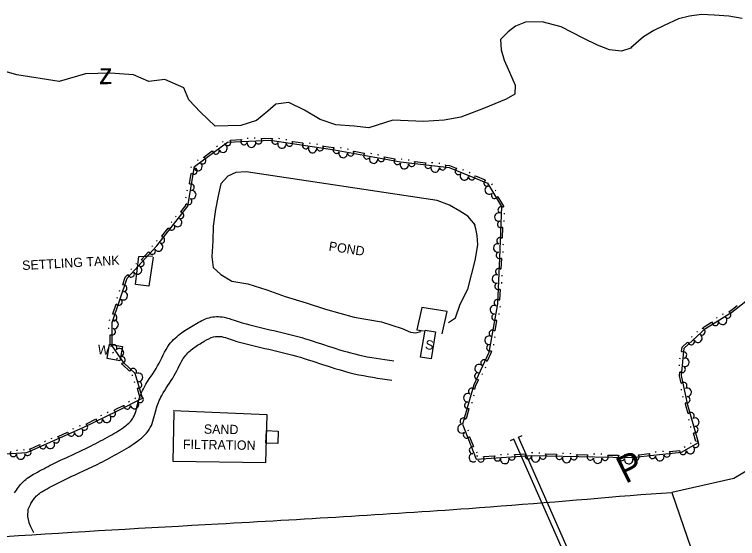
# Model space of a CAD drawing. Extents: x 2030130 to 2036320, y 723205 to 762423.
# Drawn here: x 2034679.9 to 2034966.6, y 761073.1 to 761281.1 of the extents above; entities that cross this region are included whole.
import ezdxf

# ---------------------------------------------------------------- set-up
doc = ezdxf.new("R2010")
doc.units = 0
for name, color, linetype in [('Draft_Station Labels Major', 7, 'Continuous'), ('Draft_Station Tics Major', 7, 'Continuous'), ('Draft_Station Tics Minor', 7, 'Continuous'), ('Exist Terrain Model Ground Surface', 7, 'Continuous'), ('Old_Level_28', 7, 'Continuous'), ('Prop Alignment Horizontal', 7, 'Continuous'), ('Prop Alignment Vertical', 7, 'Continuous'), ('Prop Horizontal Alignment Ramp', 7, 'Continuous')]:
    doc.layers.add(name, color=color, linetype=linetype)

msp = doc.modelspace()

# ---------------------------------------------------------------- linework, layer by layer
at = {"layer": 'Draft_Station Labels Major'}
for points in [[(2034992.98, 761113.37), (2034965.16, 761096.91), (2034940.63, 761091.38), (2034996.55, 760928.45)], [(2034928.25, 761090.56), (2034940.63, 761091.38)], [(2034686.36, 761087.04), (2034685.25, 761084.65), (2034685.11, 761081.9), (2034685.64, 761079.51), (2034686.26, 761077.85), (2034686.92, 761076.49), (2034687.39, 761075.48)]]:
    msp.add_lwpolyline(points, dxfattribs=at)
for points in [[(2034679.89, 761091.18), (2034683.28, 761095.59), (2034688.12, 761098.96), (2034694.94, 761102.58), (2034703.68, 761106.71), (2034710.37, 761109.9), (2034717.65, 761113.84), (2034723.88, 761117.76), (2034727.01, 761121.11), (2034728.85, 761126.85), (2034731.44, 761133.34), (2034736.68, 761141.63), (2034741.3, 761150.08), (2034746.26, 761154.8), (2034751.43, 761158.08), (2034757.08, 761160.74), (2034762.99, 761160.9), (2034767.05, 761159.7), (2034792.31, 761153.26), (2034816.36, 761145.98), (2034830.34, 761143.61)], [(2034686.36, 761087.04), (2034688.62, 761089.99), (2034692.11, 761092.42), (2034698.37, 761095.74), (2034706.95, 761099.8), (2034713.84, 761103.08), (2034721.52, 761107.24), (2034728.78, 761111.82), (2034733.77, 761117.13), (2034736.05, 761124.26), (2034738.28, 761129.85), (2034743.27, 761137.75), (2034747.44, 761145.36), (2034750.99, 761148.75), (2034755.12, 761151.37), (2034758.88, 761153.14), (2034761.99, 761153.22), (2034765.03, 761152.33), (2034790.26, 761145.89), (2034814.6, 761138.52), (2034829.55, 761135.98)], [(2034092.04, 760960.15), (2034128.02, 760985.27), (2034167.72, 761010.14), (2034207.02, 761028.78), (2034238.75, 761041.08), (2034290.36, 761053.26), (2034339.84, 761057.27), (2034410.92, 761061), (2034496.35, 761063.49), (2034597.04, 761068.5), (2034676.22, 761073.92), (2034760.74, 761078.95), (2034860.07, 761085.08), (2034928.36, 761090.57)]]:
    msp.add_spline(points, degree=3, dxfattribs=at)
at = {"layer": 'Draft_Station Tics Major'}
for points in [[(2034674.52, 761106.6), (2034684.82, 761107.2), (2034707.13, 761117.12), (2034720.75, 761123.81), (2034730.64, 761128.8), (2034727.79, 761138.54), (2034723.37, 761142.65), (2034718.7, 761149.56), (2034718.58, 761158.85), (2034724.55, 761176.41), (2034736.35, 761189.23), (2034748.59, 761204.98), (2034751.33, 761220.76), (2034764.42, 761230.35), (2034781.27, 761231.19), (2034806.75, 761227.39), (2034833.04, 761222.53), (2034852.26, 761220.34), (2034867.44, 761214.17), (2034872.99, 761204.81), (2034872.21, 761184.51), (2034871.4, 761166.23), (2034868.08, 761146.89), (2034862.01, 761134.08), (2034857.54, 761118.43), (2034862.96, 761104.63), (2034884.92, 761106.01), (2034909.97, 761105.46), (2034924.58, 761105.23), (2034944.38, 761107.33), (2034951.11, 761111.21), (2034946.96, 761126.03), (2034944.47, 761137.75), (2034945.43, 761148.67), (2034953.96, 761156.5), (2034964.43, 761162.91), (2034971.78, 761168.72)], [(2034762.36, 761230.37), (2034762.7, 761230.61)], [(2034765.6, 761231.23), (2034769.7, 761231.44)], [(2034772.14, 761231.97), (2034772.55, 761231.99)], [(2034775, 761232.11), (2034775.41, 761232.13)], [(2034777.89, 761231.85), (2034781.31, 761232.02), (2034782.14, 761231.89)], [(2034784.64, 761231.94), (2034785.04, 761231.88)], [(2034787.47, 761231.51), (2034787.88, 761231.45)], [(2034790.26, 761230.68), (2034794.31, 761230.08)], [(2034760.05, 761228.68), (2034760.38, 761228.92)], [(2034796.81, 761230.12), (2034797.21, 761230.06)], [(2034799.65, 761229.69), (2034800.05, 761229.63)], [(2034802.42, 761228.86), (2034806.48, 761228.26)], [(2034809, 761228.22), (2034809.41, 761228.15)], [(2034811.83, 761227.7), (2034812.23, 761227.63)], [(2034755, 761224.47), (2034758.31, 761226.89)], [(2034814.57, 761226.78), (2034818.61, 761226.03)], [(2034821.1, 761225.99), (2034821.51, 761225.91)], [(2034823.93, 761225.46), (2034824.33, 761225.39)], [(2034752.44, 761223.1), (2034752.77, 761223.35)], [(2034826.67, 761224.54), (2034830.71, 761223.79)], [(2034833.2, 761223.75), (2034833.22, 761223.74), (2034833.52, 761223.71)], [(2034835.97, 761223.43), (2034836.37, 761223.39)], [(2034838.77, 761222.7), (2034842.85, 761222.24)], [(2034845.34, 761222.37), (2034845.75, 761222.32)], [(2034848.19, 761222.04), (2034848.6, 761222)], [(2034750.01, 761220.4), (2034750.08, 761220.8)], [(2034851, 761221.31), (2034852.47, 761221.14), (2034855.1, 761220.07)], [(2034857.54, 761219.53), (2034857.92, 761219.37)], [(2034749.3, 761213.86), (2034750, 761217.9)], [(2034860.2, 761218.44), (2034860.58, 761218.29)], [(2034862.7, 761216.98), (2034866.5, 761215.44)], [(2034869.07, 761213.84), (2034869.28, 761213.49)], [(2034748.4, 761211.1), (2034748.47, 761211.51)], [(2034870.53, 761211.37), (2034870.74, 761211.02)], [(2034747.91, 761208.27), (2034747.98, 761208.67)], [(2034871.64, 761208.69), (2034873.82, 761205.02), (2034873.81, 761204.71)], [(2034745.83, 761202.77), (2034747.82, 761205.32), (2034747.89, 761205.78)], [(2034874.12, 761202.23), (2034874.11, 761201.82)], [(2034743.75, 761200.76), (2034744, 761201.08)], [(2034874.01, 761199.36), (2034874, 761198.95)], [(2034738.28, 761193.06), (2034740.8, 761196.3)], [(2034741.98, 761198.49), (2034742.24, 761198.81)], [(2034873.49, 761196.51), (2034873.33, 761192.41)], [(2034736.2, 761191.05), (2034736.45, 761191.37)], [(2034734.4, 761188.94), (2034734.68, 761189.24)], [(2034873.65, 761189.94), (2034873.63, 761189.53)], [(2034730.26, 761183.83), (2034733.04, 761186.85)], [(2034873.54, 761187.07), (2034873.52, 761186.66)], [(2034728.02, 761182), (2034728.3, 761182.3)], [(2034873.01, 761184.21), (2034872.83, 761180.11)], [(2034726.07, 761179.88), (2034726.35, 761180.18)], [(2034722.82, 761173.86), (2034723.83, 761176.84), (2034724.71, 761177.79)], [(2034873.13, 761177.64), (2034873.12, 761177.23)], [(2034873.01, 761174.77), (2034872.99, 761174.36)], [(2034721.5, 761171.27), (2034721.64, 761171.66)], [(2034872.47, 761171.92), (2034872.29, 761167.82)], [(2034720.58, 761168.55), (2034720.71, 761168.94)], [(2034718.86, 761162.21), (2034720.18, 761166.09)], [(2034872.47, 761165.21), (2034872.4, 761164.8)], [(2034963.37, 761163.23), (2034963.96, 761163.58), (2034966.56, 761165.64)], [(2034871.99, 761162.38), (2034871.92, 761161.97)], [(2034960.71, 761162.08), (2034961.06, 761162.29)], [(2034717.54, 761159.62), (2034717.68, 761160.01)], [(2034871.1, 761159.61), (2034870.4, 761155.57)], [(2034952.84, 761156.59), (2034953.46, 761157.15), (2034956.38, 761158.94)], [(2034958.26, 761160.58), (2034958.61, 761160.79)], [(2034717.38, 761156.36), (2034717.38, 761156.77)], [(2034717.88, 761149.81), (2034717.83, 761153.91)], [(2034948.33, 761153.01), (2034948.64, 761153.29)], [(2034950.45, 761154.95), (2034950.75, 761155.23)], [(2034869.91, 761150.25), (2034869.84, 761149.85)], [(2034870.39, 761153.08), (2034870.32, 761152.68)], [(2034944.48, 761147.26), (2034944.64, 761149.06), (2034946.8, 761151.05)], [(2034869.02, 761147.49), (2034868.87, 761146.64), (2034867.39, 761143.51)], [(2034719.15, 761146.7), (2034718.92, 761147.04)], [(2034720.75, 761144.33), (2034720.52, 761144.67)], [(2034943.82, 761144.44), (2034943.85, 761144.85)], [(2034725.53, 761139.53), (2034722.74, 761142.12), (2034722.47, 761142.52)], [(2034943.57, 761141.58), (2034943.6, 761141.99)], [(2034866.7, 761141.11), (2034866.53, 761140.74)], [(2034944.25, 761134.82), (2034943.64, 761137.7), (2034943.76, 761139.09)], [(2034726.76, 761137.68), (2034726.65, 761138.07)], [(2034863.87, 761136.1), (2034862.78, 761133.79), (2034862.39, 761132.43)], [(2034865.47, 761138.52), (2034865.3, 761138.14)], [(2034727.57, 761134.92), (2034727.45, 761135.32)], [(2034729.8, 761128.74), (2034728.65, 761132.67)], [(2034944.45, 761131.92), (2034944.36, 761132.32)], [(2034725.11, 761127.39), (2034725.48, 761127.57)], [(2034727.68, 761128.68), (2034728.05, 761128.87)], [(2034862.11, 761129.95), (2034862, 761129.56)], [(2034945.05, 761129.12), (2034944.96, 761129.52)], [(2034719.44, 761124.08), (2034720.38, 761124.54), (2034723.1, 761125.91)], [(2034860.14, 761124.55), (2034859.01, 761120.6)], [(2034861.32, 761127.2), (2034861.21, 761126.8)], [(2034947.02, 761122.78), (2034946.16, 761125.84), (2034945.96, 761126.79)], [(2034714.11, 761121.92), (2034714.48, 761122.1)], [(2034716.69, 761123.18), (2034717.05, 761123.36)], [(2034708.4, 761118.66), (2034712.08, 761120.47)], [(2034947.4, 761119.91), (2034947.29, 761120.3)], [(2034703.05, 761116.65), (2034703.42, 761116.82)], [(2034705.67, 761117.82), (2034706.04, 761117.98)], [(2034859.72, 761116.24), (2034859.87, 761115.86)], [(2034948.18, 761117.14), (2034948.06, 761117.54)], [(2034694.43, 761112.82), (2034694.8, 761112.98)], [(2034697.22, 761113.61), (2034700.96, 761115.28)], [(2034860.39, 761113.42), (2034861.89, 761109.6)], [(2034950.15, 761111.6), (2034949.23, 761114.88)], [(2034685.98, 761108.61), (2034689.72, 761110.28)], [(2034691.8, 761111.65), (2034692.18, 761111.82)], [(2034947.96, 761110.81), (2034948.32, 761111.02)], [(2034680.64, 761108.19), (2034681.05, 761108.21)], [(2034683.51, 761108.35), (2034683.92, 761108.38)], [(2034863.17, 761107.46), (2034863.32, 761107.08)], [(2034884.99, 761107.23), (2034885.4, 761107.23)], [(2034933.98, 761107.46), (2034934.39, 761107.51)], [(2034936.84, 761107.77), (2034937.25, 761107.81)], [(2034939.73, 761107.66), (2034943.81, 761108.09)], [(2034945.48, 761109.38), (2034945.83, 761109.58)], [(2034863.19, 761105.87), (2034863.6, 761105.9)], [(2034866.08, 761105.64), (2034870.17, 761105.9)], [(2034872.6, 761106.46), (2034873.01, 761106.49)], [(2034875.47, 761106.64), (2034875.88, 761106.67)], [(2034878.36, 761106.42), (2034882.45, 761106.67)], [(2034887.86, 761107.17), (2034888.27, 761107.16)], [(2034890.72, 761106.7), (2034894.82, 761106.61)], [(2034897.28, 761106.97), (2034897.69, 761106.96)], [(2034900.16, 761106.91), (2034900.57, 761106.9)], [(2034903.02, 761106.43), (2034907.12, 761106.35)], [(2034909.59, 761106.7), (2034910, 761106.69)], [(2034912.45, 761106.65), (2034912.86, 761106.65)], [(2034915.31, 761106.2), (2034919.41, 761106.13)], [(2034921.88, 761106.5), (2034922.29, 761106.5)], [(2034924.6, 761106.47), (2034925.01, 761106.51)], [(2034927.5, 761106.36), (2034931.58, 761106.8)]]:
    msp.add_lwpolyline(points, dxfattribs=at)
for centre, radius, start, end in [((2034764.42, 761230.35), 1.3, 201.3042, 42.1007), ((2034770.97, 761230.68), 1.3, 143.6377, 344.4343), ((2034776.7, 761230.97), 1.3, 201.3042, 42.1007), ((2034783.24, 761230.9), 1.3, 132.2751, 333.0717), ((2034788.92, 761230.05), 1.3, 189.9416, 30.7382), ((2034762.58, 761227.99), 1.69, 202.1796, 50.2521), ((2034773.88, 761230), 1.69, 168.833, 16.9055), ((2034785.96, 761229.67), 1.69, 157.4704, 5.5429), ((2034795.41, 761229.08), 1.3, 132.2751, 333.0717), ((2034798.12, 761227.85), 1.69, 157.4704, 5.5429), ((2034801.09, 761228.24), 1.3, 189.9416, 30.7382), ((2034807.57, 761227.24), 1.3, 130.289, 331.0855), ((2034759.78, 761226.96), 1.3, 176.9843, 17.7809), ((2034810.24, 761225.91), 1.69, 155.4842, 3.5567), ((2034813.22, 761226.19), 1.3, 187.9554, 28.752), ((2034819.67, 761225), 1.3, 130.289, 331.0855), ((2034752.66, 761220.72), 1.69, 202.1796, 50.2521), ((2034754.49, 761223.08), 1.3, 234.6508, 75.4474), ((2034822.34, 761223.67), 1.69, 155.4842, 3.5567), ((2034825.31, 761223.96), 1.3, 187.9554, 28.752), ((2034831.77, 761222.76), 1.3, 130.289, 331.0855), ((2034834.51, 761221.53), 1.69, 159.4806, 7.5531), ((2034837.46, 761222.02), 1.3, 191.9518, 32.7483), ((2034843.98, 761221.28), 1.3, 134.2853, 335.0819), ((2034751.02, 761218.97), 1.3, 220.9289, 61.7255), ((2034846.74, 761220.14), 1.69, 159.4806, 7.5531), ((2034849.68, 761220.64), 1.3, 191.9518, 32.7483), ((2034855.93, 761218.85), 1.3, 118.6369, 319.4334), ((2034858.29, 761217.01), 1.69, 143.8321, 351.9046), ((2034861.25, 761216.69), 1.3, 176.3033, 17.0999), ((2034749.89, 761212.51), 1.3, 278.5954, 119.392), ((2034867.33, 761214.21), 1.3, 118.6369, 319.4334), ((2034750.21, 761209.54), 1.69, 246.1242, 94.1967), ((2034868.14, 761211.38), 1.69, 106.6351, 314.7075), ((2034748.91, 761206.85), 1.3, 220.9289, 61.7255), ((2034870.31, 761209.33), 1.3, 139.1063, 339.9028), ((2034872.94, 761203.51), 1.3, 48.5421, 249.3387), ((2034745.72, 761201.3), 1.3, 250.5784, 91.3749), ((2034872.01, 761200.67), 1.69, 73.7374, 281.8099), ((2034744.61, 761198.53), 1.69, 218.1072, 66.1797), ((2034872.72, 761197.77), 1.3, 106.2086, 307.0052), ((2034742.2, 761196.76), 1.3, 192.9119, 33.7085), ((2034738.17, 761191.58), 1.3, 250.5784, 91.3749), ((2034872.47, 761191.21), 1.3, 48.5421, 249.3387), ((2034734.48, 761187.2), 1.3, 188.1536, 28.9502), ((2034737.06, 761188.81), 1.69, 218.1072, 66.1797), ((2034871.53, 761188.38), 1.69, 73.7374, 281.8099), ((2034872.24, 761185.48), 1.3, 106.2086, 307.0052), ((2034730.03, 761182.37), 1.3, 245.8201, 86.6167), ((2034728.69, 761179.7), 1.69, 213.3489, 61.4214), ((2034871.96, 761178.92), 1.3, 48.2426, 249.0391), ((2034726.15, 761178.14), 1.3, 188.1536, 28.9502), ((2034871.01, 761176.09), 1.69, 73.4378, 281.5103), ((2034723.2, 761172.43), 1.3, 269.6531, 110.4497), ((2034871.71, 761173.19), 1.3, 105.909, 306.7056), ((2034723.05, 761169.45), 1.69, 237.1819, 85.2544), ((2034721.35, 761166.99), 1.3, 211.9867, 52.7832), ((2034871.42, 761166.63), 1.3, 48.2426, 249.0391), ((2034870.17, 761163.93), 1.69, 66.2409, 274.3134), ((2034719.24, 761160.78), 1.3, 269.6531, 110.4497), ((2034870.5, 761160.97), 1.3, 98.7121, 299.5087), ((2034962.75, 761161.88), 1.3, 229.9336, 70.7302), ((2034719.41, 761158.03), 1.69, 256.7323, 104.8048), ((2034957.86, 761158.88), 1.3, 172.2672, 13.0637), ((2034960.73, 761159.69), 1.69, 197.4624, 45.5349), ((2034718.63, 761155.15), 1.3, 231.537, 72.3336), ((2034952.49, 761155.15), 1.3, 240.9506, 81.7472), ((2034868.09, 761151.81), 1.69, 66.2409, 274.3134), ((2034869.39, 761154.5), 1.3, 41.0456, 241.8422), ((2034950.93, 761152.61), 1.69, 208.4794, 56.5519), ((2034948.26, 761151.27), 1.3, 183.2842, 24.0807), ((2034719.25, 761148.75), 1.3, 322.4863, 163.2829), ((2034721.53, 761146.83), 1.69, 290.0151, 138.0876), ((2034868.42, 761148.84), 1.3, 98.7121, 299.5087), ((2034722.46, 761144), 1.3, 264.8198, 105.6164), ((2034945.19, 761145.97), 1.3, 283.4201, 124.2167), ((2034945.75, 761143.04), 1.69, 250.9489, 99.0214), ((2034864.15, 761140.51), 1.69, 50.5736, 258.6461), ((2034866.12, 761142.75), 1.3, 25.3783, 226.1749), ((2034726.99, 761139.29), 1.3, 335.5491, 176.3457), ((2034729.08, 761137.07), 1.69, 272.2258, 120.2983), ((2034863.66, 761137.56), 1.3, 83.0448, 283.8413), ((2034944.69, 761140.25), 1.3, 225.7536, 66.5502), ((2034729.09, 761134.09), 1.3, 247.0305, 87.8271), ((2034945.31, 761133.78), 1.3, 300.462, 141.2586), ((2034859.69, 761128.94), 1.69, 60.0207, 268.0932), ((2034861.26, 761131.48), 1.3, 34.8255, 235.622), ((2034946.71, 761131.15), 1.69, 267.9908, 116.0633), ((2034727.5, 761126.3), 1.69, 192.7394, 40.8119), ((2034729.7, 761128.32), 1.3, 225.2106, 66.0072), ((2034946.51, 761128.17), 1.3, 242.7956, 83.5921), ((2034724.57, 761125.74), 1.3, 167.5442, 8.3407), ((2034859.69, 761125.96), 1.3, 92.4919, 293.2885), ((2034716.49, 761120.8), 1.69, 192.1147, 40.1872), ((2034718.7, 761122.8), 1.3, 224.5859, 65.3825), ((2034948.14, 761121.82), 1.3, 304.0847, 144.8813), ((2034713.55, 761120.27), 1.3, 166.9194, 7.716), ((2034857.88, 761119.65), 1.3, 34.8255, 235.622), ((2034949.71, 761119.27), 1.69, 271.6135, 119.686), ((2034705.38, 761115.44), 1.69, 189.9417, 38.0142), ((2034707.66, 761117.38), 1.3, 224.5859, 65.3825), ((2034857.36, 761116.64), 1.69, 97.4098, 305.4823), ((2034949.69, 761116.29), 1.3, 246.4183, 87.2148), ((2034696.43, 761112.36), 1.3, 222.4129, 63.2094), ((2034702.42, 761115.03), 1.3, 164.7464, 5.543), ((2034859.17, 761114.26), 1.3, 129.881, 330.6776), ((2034691.18, 761110.03), 1.3, 164.7464, 5.543), ((2034694.14, 761110.44), 1.69, 189.9417, 38.0142), ((2034950, 761110.57), 1.3, 228.3997, 69.1962), ((2034679.49, 761106.89), 1.3, 144.1103, 344.9069), ((2034685.18, 761107.36), 1.3, 222.4129, 63.2094), ((2034861.57, 761108.16), 1.3, 72.2145, 273.0111), ((2034938.6, 761106.71), 1.3, 204.4833, 45.2799), ((2034945.03, 761107.7), 1.3, 170.7332, 11.5298), ((2034947.92, 761108.42), 1.69, 195.9285, 44.001), ((2034682.4, 761106.23), 1.69, 169.3056, 17.3781), ((2034861.86, 761105.18), 1.69, 97.4098, 305.4823), ((2034864.9, 761104.75), 1.3, 202.0305, 42.827), ((2034871.45, 761105.16), 1.3, 144.364, 345.1606), ((2034874.37, 761104.52), 1.69, 169.5593, 17.6318), ((2034877.18, 761105.52), 1.3, 202.0305, 42.827), ((2034883.73, 761105.93), 1.3, 144.364, 345.1606), ((2034886.58, 761105.15), 1.69, 164.7244, 12.7969), ((2034889.47, 761105.91), 1.3, 197.1956, 37.9921), ((2034896.03, 761105.76), 1.3, 139.5291, 340.3257), ((2034898.88, 761104.88), 1.69, 164.7244, 12.7969), ((2034901.77, 761105.64), 1.3, 197.1956, 37.9921), ((2034908.33, 761105.5), 1.3, 139.5291, 340.3257), ((2034911.19, 761104.62), 1.69, 165.0465, 13.119), ((2034914.07, 761105.4), 1.3, 197.5177, 38.3143), ((2034920.63, 761105.29), 1.3, 139.8512, 340.6478), ((2034923.49, 761104.43), 1.69, 165.0465, 13.119), ((2034926.36, 761105.42), 1.3, 204.4833, 45.2799), ((2034932.89, 761106.11), 1.3, 146.8169, 347.6134), ((2034935.83, 761105.6), 1.69, 172.0122, 20.0846)]:
    msp.add_arc(centre, radius, start, end, dxfattribs=at)
at = {"layer": 'Draft_Station Tics Minor'}
for p, q in [((2034879.78, 761113.29), (2034881.28, 761113.95)), ((2034877.98, 761112.49), (2034876.48, 761111.83))]:
    msp.add_line(p, q, dxfattribs=at)
for points in [[(2034914.38, 761034.78), (2034879.78, 761113.29)], [(2034912.57, 761033.99), (2034877.98, 761112.49)]]:
    msp.add_lwpolyline(points, dxfattribs=at)
at = {"layer": 'Exist Terrain Model Ground Surface'}
for points in [[(2034734.89, 761184.75), (2034733.12, 761173.26), (2034727.83, 761173.9), (2034729.28, 761184.96), (2034734.71, 761185.26)], [(2034849.48, 761154.35), (2034851.47, 761163.22), (2034841.5, 761164.78), (2034839.44, 761155.9), (2034842.17, 761155.58)], [(2034742.89, 761123.88), (2034779.92, 761122.31), (2034779.42, 761103.08), (2034742.89, 761103.67), (2034743.22, 761123.34)]]:
    msp.add_lwpolyline(points, dxfattribs=at)
for points in [[(2034846.88, 761155.09), (2034845.12, 761144.36), (2034840.98, 761145.03), (2034842.74, 761155.77)], [(2034722.7, 761149.36), (2034721.68, 761143.64), (2034716.61, 761144.55), (2034717.63, 761150.27)], [(2034779.84, 761115.99), (2034784.52, 761115.77), (2034784.28, 761110.78), (2034779.61, 761110.99)]]:
    msp.add_lwpolyline(points, close=True, dxfattribs=at)
at = {"layer": 'Prop Alignment Horizontal'}
for points in [[(2034968.54, 761279.41), (2034963.24, 761280.34), (2034957.34, 761280.82), (2034952.37, 761281.08), (2034947.59, 761280.35), (2034943.17, 761279.31), (2034937.6, 761276.75), (2034933.49, 761274.7), (2034929.3, 761272.18), (2034924.38, 761267.77)], [(2034924.72, 761267.89), (2034920.67, 761266.45), (2034915.83, 761267.06), (2034911.16, 761268.89), (2034905.39, 761271.61), (2034896.68, 761276.1), (2034889.12, 761278.21), (2034882.61, 761278), (2034878.57, 761276.42), (2034875.65, 761274.2), (2034872.69, 761271.16), (2034872.94, 761267.01), (2034874.05, 761262.99), (2034876.15, 761258.19), (2034878.51, 761252.99), (2034878.29, 761249.5), (2034874.87, 761247.5), (2034865.96, 761243.74), (2034856.92, 761240.34), (2034850.33, 761239.19), (2034842.07, 761238.66), (2034829.89, 761239.16), (2034820.39, 761236.12), (2034814.6, 761236.72), (2034807.37, 761237.23), (2034801.08, 761239.39), (2034794.9, 761243.14), (2034788.68, 761246.13), (2034783.6, 761245.51), (2034780.31, 761242.65), (2034775.89, 761239.02), (2034769.72, 761236.96), (2034759.45, 761236.77), (2034753.64, 761242.35), (2034749.08, 761247.23), (2034747.11, 761251.94), (2034739.58, 761255.32), (2034733.14, 761254.47), (2034727.05, 761257.17), (2034717.81, 761257.77), (2034708.03, 761257.45), (2034697.68, 761254.53), (2034680.79, 761257.12), (2034668.83, 761260.56)], [(2034862.56, 761197.63), (2034859.64, 761200.98), (2034856.5, 761203.05), (2034852.41, 761205.34), (2034847.47, 761207.28), (2034771.79, 761218.61), (2034767.64, 761218.31), (2034764.53, 761216.92), (2034761.71, 761213.86), (2034760.65, 761209.13), (2034759.58, 761203.63), (2034758.73, 761197.09), (2034758.58, 761191.24), (2034758.21, 761184.85), (2034758.66, 761180.66), (2034761.7, 761177.88), (2034766.16, 761175.2), (2034772.49, 761174.24), (2034780.02, 761171.79), (2034787.31, 761169.17), (2034795.6, 761166.59), (2034803.23, 761164.12), (2034814.62, 761160.9), (2034825.48, 761159.13), (2034833.71, 761156.43), (2034836.95, 761154.95), (2034839.05, 761154.77), (2034841.1, 761155.26)], [(2034852, 761158.78), (2034854.8, 761160.74), (2034856.66, 761166.05), (2034859.72, 761172.1), (2034862.62, 761183.43), (2034863.59, 761189.64), (2034863.41, 761193.41), (2034862.9, 761196.03), (2034862.28, 761197.94)]]:
    msp.add_lwpolyline(points, dxfattribs=at)

# ---------------------------------------------------------------- texts
at = {"layer": 'Old_Level_28'}
for s, height, rotation, p in [('SETTLING TANK', 3.6909, 3.1505, (2034683.04, 761179.63)), ('S', 3.69, 351.8688, (2034842.58, 761148.34)), ('W', 3.69, 354.1116, (2034712.73, 761146.38)), ('SAND', 3.691, 359.1345, (2034754.97, 761114.71)), ('FILTRATION', 3.691, 359.1345, (2034746.68, 761108.68))]:
    msp.add_text(s, height=height, rotation=rotation, dxfattribs=at).set_placement(p)
at = {"layer": 'Prop Alignment Horizontal'}
msp.add_text('z', height=8.2, rotation=0.1809, dxfattribs=at).set_placement((2034713.42, 761253.4))
at = {"layer": 'Prop Alignment Vertical'}
msp.add_text('POND', height=3.691, rotation=351.3791, dxfattribs=at).set_placement((2034804.35, 761187.37))
at = {"layer": 'Prop Horizontal Alignment Ramp'}
msp.add_text('P', height=10.66, rotation=26.3279, dxfattribs=at).set_placement((2034922.15, 761094.71))

doc.saveas('drawing.dxf')
